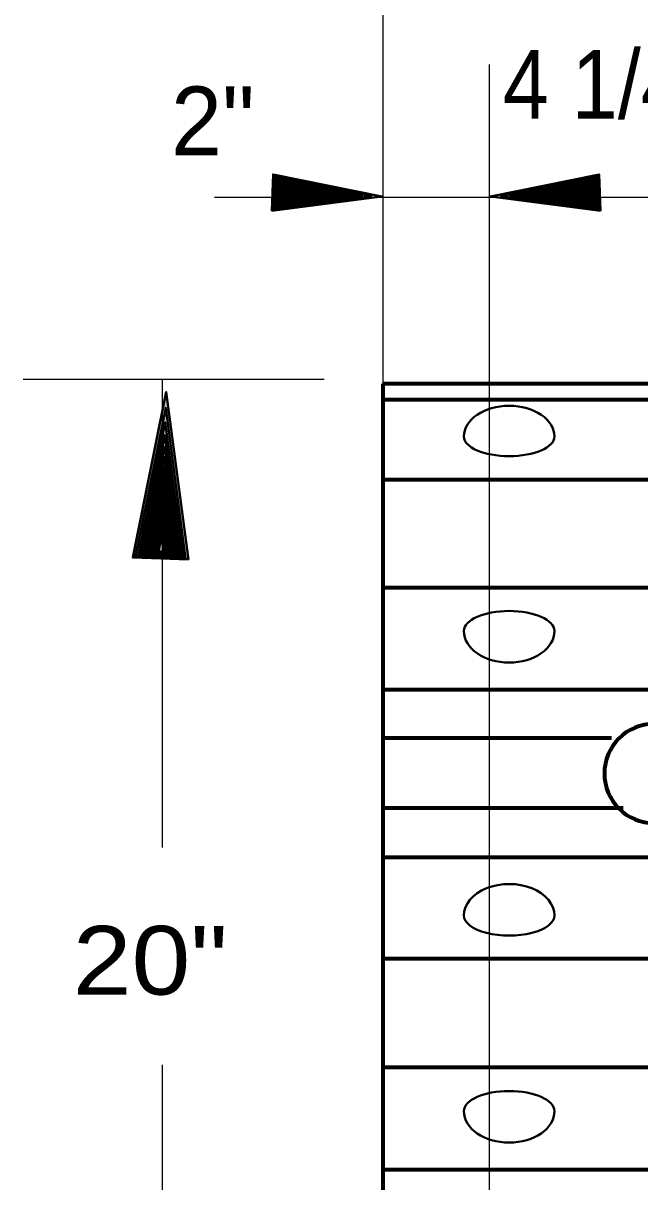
# Model space of a CAD drawing. Extents: x 895.6 to 930.4, y -2278.6 to -2254.7.
# Drawn here: x 911.763 to 912.917, y -2261.783 to -2259.614 of the extents above; entities that cross this region are included whole.
import ezdxf

# ---------------------------------------------------------------- set-up
doc = ezdxf.new("R2010")
doc.units = 0
doc.header["$LTSCALE"] = 0.051
doc.layers.add('1', color=7, linetype='Continuous', lineweight=70)
doc.layers.add('3', color=7, linetype='Continuous', lineweight=40)

msp = doc.modelspace()

# ---------------------------------------------------------------- hatches: boundary and pattern name
at = {"layer": '3'}
for points in [[(912.22792, -2259.96517), (912.23033, -2259.89683), (912.43375, -2259.93792), (912.43375, -2259.93792)], [(912.22892, -2259.96167), (912.23108, -2259.90025), (912.41417, -2259.93717), (912.41417, -2259.93717)], [(912.84275, -2259.96517), (912.84033, -2259.89683), (912.63692, -2259.93792), (912.63692, -2259.93792)], [(912.84175, -2259.96167), (912.83967, -2259.90025), (912.65658, -2259.93717), (912.65658, -2259.93717)], [(912.22983, -2259.95867), (912.23175, -2259.90342), (912.39658, -2259.93675), (912.39658, -2259.93675)], [(912.23075, -2259.95592), (912.23242, -2259.90625), (912.38083, -2259.93617), (912.38083, -2259.93617)], [(912.23142, -2259.95358), (912.23308, -2259.90883), (912.36658, -2259.93575), (912.36658, -2259.93575)], [(912.23233, -2259.95133), (912.23367, -2259.91092), (912.35375, -2259.93525), (912.35375, -2259.93525)], [(912.23283, -2259.94917), (912.23392, -2259.91292), (912.34217, -2259.93483), (912.34217, -2259.93483)], [(912.23342, -2259.94758), (912.23442, -2259.91483), (912.33167, -2259.93442), (912.33167, -2259.93442)], [(912.23375, -2259.94592), (912.23492, -2259.91642), (912.32242, -2259.93417), (912.32242, -2259.93417)], [(912.23433, -2259.94433), (912.23525, -2259.91783), (912.31408, -2259.93383), (912.31408, -2259.93383)], [(912.23475, -2259.94317), (912.23558, -2259.91925), (912.30642, -2259.93367), (912.30642, -2259.93367)], [(912.23508, -2259.94175), (912.23592, -2259.92067), (912.29967, -2259.93333), (912.29967, -2259.93333)], [(912.23542, -2259.94092), (912.23608, -2259.92158), (912.29342, -2259.93317), (912.29342, -2259.93317)], [(912.23592, -2259.93983), (912.23625, -2259.92258), (912.28808, -2259.93308), (912.28808, -2259.93308)], [(912.23608, -2259.93908), (912.23667, -2259.92342), (912.28308, -2259.93283), (912.28308, -2259.93283)], [(912.23625, -2259.93825), (912.23675, -2259.92417), (912.27858, -2259.93258), (912.27858, -2259.93258)], [(912.84083, -2259.95867), (912.83892, -2259.90342), (912.67417, -2259.93675), (912.67417, -2259.93675)], [(912.83992, -2259.95592), (912.83825, -2259.90625), (912.68983, -2259.93617), (912.68983, -2259.93617)], [(912.83925, -2259.95358), (912.83767, -2259.90883), (912.70417, -2259.93575), (912.70417, -2259.93575)], [(912.83833, -2259.95133), (912.83708, -2259.91092), (912.71692, -2259.93525), (912.71692, -2259.93525)], [(912.83783, -2259.94917), (912.83675, -2259.91292), (912.72858, -2259.93483), (912.72858, -2259.93483)], [(912.83725, -2259.94758), (912.83625, -2259.91483), (912.73908, -2259.93442), (912.73908, -2259.93442)], [(912.83692, -2259.94592), (912.83575, -2259.91642), (912.74825, -2259.93417), (912.74825, -2259.93417)], [(912.83633, -2259.94433), (912.83542, -2259.91783), (912.75667, -2259.93383), (912.75667, -2259.93383)], [(912.83592, -2259.94317), (912.83517, -2259.91925), (912.76425, -2259.93367), (912.76425, -2259.93367)], [(912.83567, -2259.94175), (912.83475, -2259.92067), (912.77108, -2259.93333), (912.77108, -2259.93333)], [(912.83525, -2259.94092), (912.83467, -2259.92158), (912.77725, -2259.93317), (912.77725, -2259.93317)], [(912.83475, -2259.93983), (912.83442, -2259.92258), (912.78267, -2259.93308), (912.78267, -2259.93308)], [(912.83467, -2259.93908), (912.83408, -2259.92342), (912.78767, -2259.93283), (912.78767, -2259.93283)], [(912.83442, -2259.93825), (912.83392, -2259.92417), (912.79217, -2259.93258), (912.79217, -2259.93258)], [(912.23658, -2259.93758), (912.23683, -2259.92475), (912.27467, -2259.93242), (912.27467, -2259.93242)], [(912.23675, -2259.93692), (912.23692, -2259.92558), (912.27108, -2259.93233), (912.27108, -2259.93233)], [(912.23683, -2259.93658), (912.23717, -2259.92625), (912.26775, -2259.93233), (912.26775, -2259.93233)], [(912.23708, -2259.93608), (912.23742, -2259.92675), (912.26492, -2259.93233), (912.26492, -2259.93233)], [(912.23733, -2259.93575), (912.23767, -2259.92725), (912.26233, -2259.93242), (912.26233, -2259.93242)], [(912.23733, -2259.93525), (912.23767, -2259.92783), (912.25992, -2259.93233), (912.25992, -2259.93233)], [(912.23758, -2259.93475), (912.23775, -2259.92808), (912.25783, -2259.93208), (912.25783, -2259.93208)], [(912.23767, -2259.93442), (912.23775, -2259.92867), (912.25583, -2259.93217), (912.25583, -2259.93217)], [(912.83417, -2259.93758), (912.83383, -2259.92475), (912.79608, -2259.93242), (912.79608, -2259.93242)], [(912.83392, -2259.93692), (912.83375, -2259.92558), (912.79967, -2259.93233), (912.79967, -2259.93233)], [(912.83383, -2259.93658), (912.83358, -2259.92625), (912.80292, -2259.93233), (912.80292, -2259.93233)], [(912.83367, -2259.93608), (912.83325, -2259.92675), (912.80575, -2259.93233), (912.80575, -2259.93233)], [(912.83333, -2259.93575), (912.83308, -2259.92725), (912.80833, -2259.93242), (912.80833, -2259.93242)], [(912.83333, -2259.93525), (912.83308, -2259.92783), (912.81075, -2259.93233), (912.81075, -2259.93233)], [(912.83317, -2259.93475), (912.83292, -2259.92808), (912.81283, -2259.93208), (912.81283, -2259.93208)], [(912.83308, -2259.93442), (912.83292, -2259.92867), (912.81483, -2259.93217), (912.81483, -2259.93217)], [(912.07175, -2260.61758), (911.96775, -2260.61408), (912.03033, -2260.30392), (912.03033, -2260.30392)], [(912.06658, -2260.61608), (911.97292, -2260.61275), (912.02933, -2260.33367), (912.02933, -2260.33367)], [(912.06183, -2260.61458), (911.97775, -2260.61175), (912.02842, -2260.36058), (912.02842, -2260.36058)], [(912.05775, -2260.61333), (911.98208, -2260.61075), (912.02767, -2260.38458), (912.02767, -2260.38458)], [(912.05417, -2260.61225), (911.98592, -2260.60992), (912.02692, -2260.40625), (912.02692, -2260.40625)], [(912.05067, -2260.61092), (911.98933, -2260.60908), (912.02633, -2260.42575), (912.02633, -2260.42575)], [(912.04758, -2260.61017), (911.99242, -2260.60833), (912.02575, -2260.44342), (912.02575, -2260.44342)], [(912.04492, -2260.60917), (911.99517, -2260.60767), (912.02517, -2260.45933), (912.02517, -2260.45933)], [(912.04258, -2260.60867), (911.99767, -2260.60708), (912.02458, -2260.47342), (912.02458, -2260.47342)], [(912.04017, -2260.60775), (911.99975, -2260.60633), (912.02417, -2260.48642), (912.02417, -2260.48642)], [(912.03833, -2260.60725), (912.00192, -2260.60592), (912.02383, -2260.49792), (912.02383, -2260.49792)], [(912.03642, -2260.60667), (912.00383, -2260.60542), (912.02333, -2260.50825), (912.02333, -2260.50825)], [(912.03483, -2260.60617), (912.00542, -2260.60517), (912.02308, -2260.51775), (912.02308, -2260.51775)], [(912.03333, -2260.60542), (912.00683, -2260.60483), (912.02283, -2260.52608), (912.02283, -2260.52608)], [(912.03208, -2260.60525), (912.00825, -2260.60442), (912.02267, -2260.53358), (912.02267, -2260.53358)], [(912.03083, -2260.60475), (912.00942, -2260.60425), (912.02225, -2260.54033), (912.02225, -2260.54033)], [(912.02975, -2260.60458), (912.01042, -2260.60383), (912.02208, -2260.54642), (912.02208, -2260.54642)], [(912.02875, -2260.60433), (912.01142, -2260.60367), (912.02183, -2260.55192), (912.02183, -2260.55192)], [(912.02825, -2260.60383), (912.01242, -2260.60358), (912.02183, -2260.55683), (912.02183, -2260.55683)], [(912.02758, -2260.60367), (912.01333, -2260.60317), (912.02175, -2260.56125), (912.02175, -2260.56125)], [(912.02692, -2260.60325), (912.01425, -2260.60275), (912.02192, -2260.56517), (912.02192, -2260.56517)], [(912.02625, -2260.60325), (912.01492, -2260.60275), (912.02175, -2260.56883), (912.02175, -2260.56883)], [(912.02567, -2260.60308), (912.01542, -2260.60267), (912.02142, -2260.57217), (912.02142, -2260.57217)], [(912.02517, -2260.60275), (912.01608, -2260.60258), (912.02158, -2260.57492), (912.02158, -2260.57492)]]:
    msp.add_hatch(color=256, dxfattribs=at).paths.add_polyline_path(points)

# ---------------------------------------------------------------- linework, layer by layer
at = {"layer": '1', "lineweight": 25}
for p, q in [((912.43625, -2260.80017), (912.43625, -2258.55592)), ((912.63517, -2262.92192), (912.63517, -2259.69075)), ((912.12067, -2259.93958), (913.71608, -2259.93958)), ((911.76258, -2260.27992), (912.32575, -2260.27992)), ((912.02342, -2261.15692), (912.02342, -2260.27967)), ((912.02342, -2262.65267), (912.02342, -2261.56383))]:
    msp.add_line(p, q, dxfattribs=at)
at = {"layer": '1'}
for p, q in [((912.43592, -2260.28858), (912.43592, -2262.64575)), ((913.85217, -2260.28858), (912.43592, -2260.28858)), ((912.43625, -2260.31833), (913.85217, -2260.31833)), ((913.85217, -2260.46825), (912.43592, -2260.46825)), ((913.85217, -2260.67058), (912.43592, -2260.67058)), ((913.85217, -2260.86133), (912.43592, -2260.86133)), ((912.86342, -2260.95208), (912.43592, -2260.95208)), ((912.88575, -2261.08342), (912.43592, -2261.08342)), ((913.85217, -2261.17567), (912.43592, -2261.17567)), ((913.95217, -2261.36533), (912.43592, -2261.36533)), ((913.97317, -2261.56875), (912.43592, -2261.56875)), ((913.85217, -2261.75992), (912.43592, -2261.75992))]:
    msp.add_line(p, q, dxfattribs=at)
msp.add_arc((912.94323, -2261.01826), 0.09303, 90, 270, dxfattribs=at)
at = {"layer": '1', "lineweight": 40}
for centre, major_axis, ratio, start_param, end_param in [((912.67212, -2260.38744), (-0.08469, 0), 0.679978, 3.1415927, 6.2831853), ((912.67212, -2260.38744), (0.08469, 0), 0.434256, 3.1415927, 6.2831853), ((912.67212, -2260.75152), (-0.08469, 0), 0.442883, 3.1415927, 6.2831853), ((912.67212, -2260.75152), (0.08469, 0), 0.696674, 3.1415927, 6.2831853), ((912.67212, -2261.28416), (0.08469, 0), 0.696674, 6.2831853, 9.424778), ((912.67212, -2261.28416), (-0.08469, 0), 0.442883, 6.2831853, 9.424778), ((912.67212, -2261.65024), (-0.08469, 0), 0.442883, 3.1415927, 6.2831853), ((912.67212, -2261.65024), (0.08469, 0), 0.696674, 3.1415927, 6.2831853)]:
    msp.add_ellipse(centre, major_axis=major_axis, ratio=ratio, start_param=start_param, end_param=end_param, dxfattribs=at)
at = {"layer": '3'}
for points in [[(912.22792, -2259.96517), (912.23033, -2259.89683), (912.43375, -2259.93792), (912.43375, -2259.93792)], [(912.22892, -2259.96167), (912.23108, -2259.90025), (912.41417, -2259.93717), (912.41417, -2259.93717)], [(912.84275, -2259.96517), (912.84033, -2259.89683), (912.63692, -2259.93792), (912.63692, -2259.93792)], [(912.84175, -2259.96167), (912.83967, -2259.90025), (912.65658, -2259.93717), (912.65658, -2259.93717)], [(912.22983, -2259.95867), (912.23175, -2259.90342), (912.39658, -2259.93675), (912.39658, -2259.93675)], [(912.23075, -2259.95592), (912.23242, -2259.90625), (912.38083, -2259.93617), (912.38083, -2259.93617)], [(912.23142, -2259.95358), (912.23308, -2259.90883), (912.36658, -2259.93575), (912.36658, -2259.93575)], [(912.23233, -2259.95133), (912.23367, -2259.91092), (912.35375, -2259.93525), (912.35375, -2259.93525)], [(912.23283, -2259.94917), (912.23392, -2259.91292), (912.34217, -2259.93483), (912.34217, -2259.93483)], [(912.23342, -2259.94758), (912.23442, -2259.91483), (912.33167, -2259.93442), (912.33167, -2259.93442)], [(912.23375, -2259.94592), (912.23492, -2259.91642), (912.32242, -2259.93417), (912.32242, -2259.93417)], [(912.23433, -2259.94433), (912.23525, -2259.91783), (912.31408, -2259.93383), (912.31408, -2259.93383)], [(912.23475, -2259.94317), (912.23558, -2259.91925), (912.30642, -2259.93367), (912.30642, -2259.93367)], [(912.23508, -2259.94175), (912.23592, -2259.92067), (912.29967, -2259.93333), (912.29967, -2259.93333)], [(912.23542, -2259.94092), (912.23608, -2259.92158), (912.29342, -2259.93317), (912.29342, -2259.93317)], [(912.23592, -2259.93983), (912.23625, -2259.92258), (912.28808, -2259.93308), (912.28808, -2259.93308)], [(912.23608, -2259.93908), (912.23667, -2259.92342), (912.28308, -2259.93283), (912.28308, -2259.93283)], [(912.23625, -2259.93825), (912.23675, -2259.92417), (912.27858, -2259.93258), (912.27858, -2259.93258)], [(912.84083, -2259.95867), (912.83892, -2259.90342), (912.67417, -2259.93675), (912.67417, -2259.93675)], [(912.83992, -2259.95592), (912.83825, -2259.90625), (912.68983, -2259.93617), (912.68983, -2259.93617)], [(912.83925, -2259.95358), (912.83767, -2259.90883), (912.70417, -2259.93575), (912.70417, -2259.93575)], [(912.83833, -2259.95133), (912.83708, -2259.91092), (912.71692, -2259.93525), (912.71692, -2259.93525)], [(912.83783, -2259.94917), (912.83675, -2259.91292), (912.72858, -2259.93483), (912.72858, -2259.93483)], [(912.83725, -2259.94758), (912.83625, -2259.91483), (912.73908, -2259.93442), (912.73908, -2259.93442)], [(912.83692, -2259.94592), (912.83575, -2259.91642), (912.74825, -2259.93417), (912.74825, -2259.93417)], [(912.83633, -2259.94433), (912.83542, -2259.91783), (912.75667, -2259.93383), (912.75667, -2259.93383)], [(912.83592, -2259.94317), (912.83517, -2259.91925), (912.76425, -2259.93367), (912.76425, -2259.93367)], [(912.83567, -2259.94175), (912.83475, -2259.92067), (912.77108, -2259.93333), (912.77108, -2259.93333)], [(912.83525, -2259.94092), (912.83467, -2259.92158), (912.77725, -2259.93317), (912.77725, -2259.93317)], [(912.83475, -2259.93983), (912.83442, -2259.92258), (912.78267, -2259.93308), (912.78267, -2259.93308)], [(912.83467, -2259.93908), (912.83408, -2259.92342), (912.78767, -2259.93283), (912.78767, -2259.93283)], [(912.83442, -2259.93825), (912.83392, -2259.92417), (912.79217, -2259.93258), (912.79217, -2259.93258)], [(912.23658, -2259.93758), (912.23683, -2259.92475), (912.27467, -2259.93242), (912.27467, -2259.93242)], [(912.23675, -2259.93692), (912.23692, -2259.92558), (912.27108, -2259.93233), (912.27108, -2259.93233)], [(912.23683, -2259.93658), (912.23717, -2259.92625), (912.26775, -2259.93233), (912.26775, -2259.93233)], [(912.23708, -2259.93608), (912.23742, -2259.92675), (912.26492, -2259.93233), (912.26492, -2259.93233)], [(912.23733, -2259.93575), (912.23767, -2259.92725), (912.26233, -2259.93242), (912.26233, -2259.93242)], [(912.23733, -2259.93525), (912.23767, -2259.92783), (912.25992, -2259.93233), (912.25992, -2259.93233)], [(912.23758, -2259.93475), (912.23775, -2259.92808), (912.25783, -2259.93208), (912.25783, -2259.93208)], [(912.23767, -2259.93442), (912.23775, -2259.92867), (912.25583, -2259.93217), (912.25583, -2259.93217)], [(912.83417, -2259.93758), (912.83383, -2259.92475), (912.79608, -2259.93242), (912.79608, -2259.93242)], [(912.83392, -2259.93692), (912.83375, -2259.92558), (912.79967, -2259.93233), (912.79967, -2259.93233)], [(912.83383, -2259.93658), (912.83358, -2259.92625), (912.80292, -2259.93233), (912.80292, -2259.93233)], [(912.83367, -2259.93608), (912.83325, -2259.92675), (912.80575, -2259.93233), (912.80575, -2259.93233)], [(912.83333, -2259.93575), (912.83308, -2259.92725), (912.80833, -2259.93242), (912.80833, -2259.93242)], [(912.83333, -2259.93525), (912.83308, -2259.92783), (912.81075, -2259.93233), (912.81075, -2259.93233)], [(912.83317, -2259.93475), (912.83292, -2259.92808), (912.81283, -2259.93208), (912.81283, -2259.93208)], [(912.83308, -2259.93442), (912.83292, -2259.92867), (912.81483, -2259.93217), (912.81483, -2259.93217)], [(912.07175, -2260.61758), (911.96775, -2260.61408), (912.03033, -2260.30392), (912.03033, -2260.30392)], [(912.06658, -2260.61608), (911.97292, -2260.61275), (912.02933, -2260.33367), (912.02933, -2260.33367)], [(912.06183, -2260.61458), (911.97775, -2260.61175), (912.02842, -2260.36058), (912.02842, -2260.36058)], [(912.05775, -2260.61333), (911.98208, -2260.61075), (912.02767, -2260.38458), (912.02767, -2260.38458)], [(912.05417, -2260.61225), (911.98592, -2260.60992), (912.02692, -2260.40625), (912.02692, -2260.40625)], [(912.05067, -2260.61092), (911.98933, -2260.60908), (912.02633, -2260.42575), (912.02633, -2260.42575)], [(912.04758, -2260.61017), (911.99242, -2260.60833), (912.02575, -2260.44342), (912.02575, -2260.44342)], [(912.04492, -2260.60917), (911.99517, -2260.60767), (912.02517, -2260.45933), (912.02517, -2260.45933)], [(912.04258, -2260.60867), (911.99767, -2260.60708), (912.02458, -2260.47342), (912.02458, -2260.47342)], [(912.04017, -2260.60775), (911.99975, -2260.60633), (912.02417, -2260.48642), (912.02417, -2260.48642)], [(912.03833, -2260.60725), (912.00192, -2260.60592), (912.02383, -2260.49792), (912.02383, -2260.49792)], [(912.03642, -2260.60667), (912.00383, -2260.60542), (912.02333, -2260.50825), (912.02333, -2260.50825)], [(912.03483, -2260.60617), (912.00542, -2260.60517), (912.02308, -2260.51775), (912.02308, -2260.51775)], [(912.03333, -2260.60542), (912.00683, -2260.60483), (912.02283, -2260.52608), (912.02283, -2260.52608)], [(912.03208, -2260.60525), (912.00825, -2260.60442), (912.02267, -2260.53358), (912.02267, -2260.53358)], [(912.03083, -2260.60475), (912.00942, -2260.60425), (912.02225, -2260.54033), (912.02225, -2260.54033)], [(912.02975, -2260.60458), (912.01042, -2260.60383), (912.02208, -2260.54642), (912.02208, -2260.54642)], [(912.02875, -2260.60433), (912.01142, -2260.60367), (912.02183, -2260.55192), (912.02183, -2260.55192)], [(912.02825, -2260.60383), (912.01242, -2260.60358), (912.02183, -2260.55683), (912.02183, -2260.55683)], [(912.02758, -2260.60367), (912.01333, -2260.60317), (912.02175, -2260.56125), (912.02175, -2260.56125)], [(912.02692, -2260.60325), (912.01425, -2260.60275), (912.02192, -2260.56517), (912.02192, -2260.56517)], [(912.02625, -2260.60325), (912.01492, -2260.60275), (912.02175, -2260.56883), (912.02175, -2260.56883)], [(912.02567, -2260.60308), (912.01542, -2260.60267), (912.02142, -2260.57217), (912.02142, -2260.57217)], [(912.02517, -2260.60275), (912.01608, -2260.60258), (912.02158, -2260.57492), (912.02158, -2260.57492)]]:
    msp.add_lwpolyline(points, close=True, dxfattribs=at)

# ---------------------------------------------------------------- texts
at = {"layer": '1'}
for s, width, p in [('4 1/4"', 0.9, (912.66033, -2259.79233)), ('20"', 1.15, (911.85542, -2261.43225))]:
    msp.add_text(s, height=0.1286, dxfattribs=dict(at, width=width)).set_placement(p)
msp.add_text('2"', height=0.1286, dxfattribs=at).set_placement((912.03917, -2259.86075))

doc.saveas('drawing.dxf')
